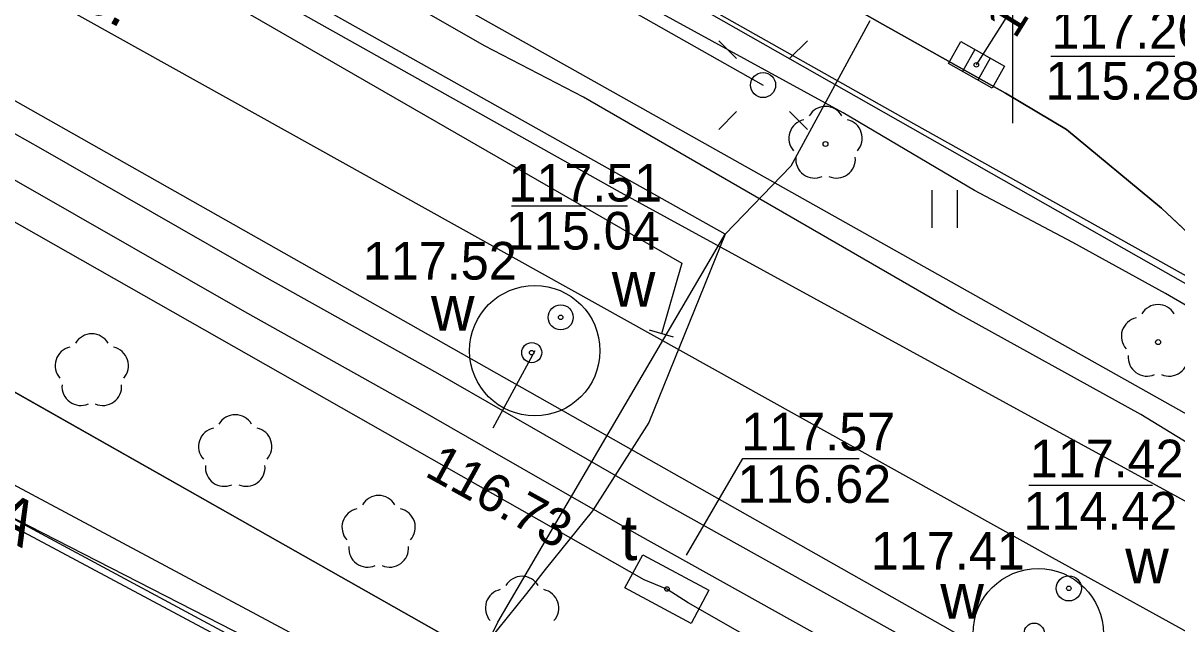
# Model space of a CAD drawing. Extents: x 6434771 to 6436222, y 5663454 to 5664782.
# Drawn here: x 6435180.26 to 6435203.28, y 5663885.02 to 5663897 of the extents above; entities that cross this region are included whole.
import ezdxf

# ---------------------------------------------------------------- set-up
doc = ezdxf.new("R2010")
doc.units = 0
for name, color, linetype in [('Warstwa 1', 7, 'Continuous'), ('Warstwa 10', 7, 'Continuous'), ('Warstwa 11', 7, 'Continuous'), ('Warstwa 12', 7, 'Continuous'), ('Warstwa 13', 7, 'Continuous'), ('Warstwa 14', 7, 'Continuous'), ('Warstwa 15', 7, 'Continuous'), ('Warstwa 2', 7, 'Continuous'), ('Warstwa 20', 7, 'Continuous'), ('Warstwa 4', 7, 'Continuous'), ('Warstwa 5', 7, 'Continuous'), ('Warstwa 6', 7, 'Continuous'), ('Warstwa 63', 7, 'Continuous'), ('Warstwa 7', 7, 'Continuous'), ('Warstwa 8', 7, 'Continuous'), ('Warstwa 9', 7, 'Continuous')]:
    doc.layers.add(name, color=color, linetype=linetype)

msp = doc.modelspace()

# ---------------------------------------------------------------- linework, layer by layer
at = {"layer": 'Warstwa 1'}
msp.add_line((6435069.683, 5663952.11), (6435199.169, 5663878.85), dxfattribs=at)
msp.add_line((6435069.683, 5663952.11), (6435199.169, 5663878.85), dxfattribs=at)
at = {"layer": 'Warstwa 10'}
for points in [[(6435097.639, 5663946.244), (6435110.23, 5663939.33), (6435134.8, 5663925.67), (6435154.54, 5663914.28), (6435171.5, 5663904.82), (6435193.4, 5663892.21), (6435192.998, 5663890.805)], [(6435182.257, 5663838.676), (6435188.304, 5663849.448), (6435193.351, 5663858.439), (6435194.278, 5663859.798), (6435191.577, 5663860.571), (6435190.64, 5663861.662), (6435194.242, 5663871.739), (6435194.776, 5663876.163), (6435192.223, 5663879.254), (6435189.657, 5663881.265), (6435188.718, 5663882.987), (6435189.733, 5663885.054), (6435194.267, 5663892.79), (6435145.165, 5663920.315), (6435099.449, 5663946.22)], [(6435276.336, 5663842.501), (6435260.05, 5663851.86), (6435249.96, 5663857.64), (6435238.71, 5663863.53), (6435238.1, 5663863.95), (6435237.79, 5663864.33), (6435236.77, 5663866.27), (6435229, 5663870.99), (6435224.85, 5663875.36), (6435224.07, 5663876.18), (6435215.14, 5663881.13), (6435208.14, 5663884.9), (6435192.12, 5663893.65), (6435170.67, 5663905.68), (6435152.15, 5663915.89), (6435146.79, 5663915.59), (6435128.02, 5663926.23), (6435125.23, 5663931.72), (6435111.04, 5663939.84), (6435099.552, 5663946.221)], [(6435276.398, 5663847.572), (6435270.914, 5663850.621), (6435269.128, 5663851.761), (6435267.523, 5663852.588), (6435261.727, 5663855.858), (6435256.855, 5663858.651), (6435248.36, 5663863.366), (6435242.1, 5663866.891), (6435238.077, 5663869.191), (6435236.318, 5663870.082), (6435231.153, 5663872.984), (6435227.254, 5663875.255), (6435219.004, 5663879.813), (6435214.473, 5663882.474), (6435208.6, 5663885.825), (6435204.743, 5663887.86), (6435202.556, 5663889.192), (6435198.825, 5663891.256), (6435191.441, 5663895.523), (6435189.466, 5663896.541), (6435185.427, 5663898.858)]]:
    msp.add_lwpolyline(points, dxfattribs=at)
at = {"layer": 'Warstwa 11'}
for centre in [(6435196.269, 5663894.586), (6435202.902, 5663890.636)]:
    msp.add_circle(centre, 0.05, dxfattribs=at)
for centre, start, end in [((6435196.269, 5663894.961), 30.1471, 149.8529), ((6435195.912, 5663894.702), 102.1471, 221.8529), ((6435196.626, 5663894.702), 318.1471, 77.8529), ((6435196.049, 5663894.283), 174.1471, 293.8529), ((6435196.489, 5663894.283), 246.1471, 5.8529), ((6435202.902, 5663891.011), 30.1471, 149.8529), ((6435202.545, 5663890.752), 102.1471, 221.8529), ((6435202.682, 5663890.333), 174.1471, 293.8529), ((6435203.122, 5663890.333), 246.1471, 5.8529)]:
    msp.add_arc(centre, 0.375, start, end, dxfattribs=at)
at = {"layer": 'Warstwa 12'}
for points in [[(6435276.296, 5663839.122), (6435202.248, 5663880.463), (6435193.528, 5663885.439), (6435193.106, 5663885.714), (6435192.653, 5663885.899), (6435159.975, 5663904.455), (6435111.809, 5663931.659), (6435087.394, 5663945.495), (6435086.953, 5663945.766), (6435086.601, 5663946.025), (6435086.024, 5663946.382)], [(6435105.187, 5663946.15), (6435115.17, 5663940.769), (6435143.559, 5663924.775), (6435168.541, 5663910.722), (6435195.023, 5663895.761)], [(6435221.655, 5663880.269), (6435221.936, 5663880.862), (6435218.575, 5663882.674), (6435218.173, 5663882.896), (6435217.302, 5663882.72), (6435214.097, 5663884.591), (6435205.693, 5663889.213), (6435205.45, 5663889.713), (6435204.961, 5663890.309), (6435204.469, 5663890.781), (6435203.051, 5663891.606), (6435201.201, 5663892.622), (6435199.242, 5663893.656), (6435196.622, 5663895.21), (6435191.749, 5663897.878), (6435189.16, 5663899.338), (6435182.205, 5663903.135), (6435181.651, 5663903.483), (6435176.748, 5663906.246), (6435171.243, 5663909.279), (6435113.962, 5663942.157), (6435109.55, 5663944.447), (6435106.279, 5663946.137)], [(6435107.26, 5663946.125), (6435127.986, 5663934.544), (6435149.124, 5663922.599), (6435165.622, 5663913.277), (6435237.784, 5663872.323), (6435252.455, 5663863.225), (6435276.408, 5663848.377)], [(6435063.696, 5663930.091), (6435072.471, 5663935.396), (6435084.159, 5663937.604), (6435099.338, 5663932.48), (6435124.367, 5663918.137), (6435165.517, 5663894.728), (6435170.23, 5663892.401), (6435196.432, 5663878.313), (6435197.764, 5663876.037), (6435200.507, 5663874.574)], [(6435243.45, 5663833.342), (6435243.347, 5663833.392), (6435243.041, 5663835.668), (6435233.883, 5663842.599), (6435229.544, 5663847.621), (6435230.488, 5663855.43), (6435227.071, 5663861.482), (6435200.606, 5663877.013), (6435196.659, 5663878.93), (6435171.937, 5663892.14), (6435164.739, 5663895.707), (6435120.054, 5663921.259), (6435106.974, 5663928.778), (6435090.917, 5663933.312), (6435076.731, 5663934.584), (6435064.319, 5663933.634), (6435061.286, 5663934.067)], [(6435184.91, 5663855.561), (6435186.088, 5663855.747), (6435193.004, 5663868.644), (6435194.726, 5663873.753), (6435194.748, 5663876.343), (6435193.834, 5663878.494), (6435189.316, 5663882.019), (6435172.175, 5663891.167), (6435167.238, 5663893.957), (6435152.766, 5663902.142), (6435132.535, 5663913.808), (6435121.373, 5663919.463), (6435119.301, 5663920.188), (6435117.575, 5663919.659), (6435117.521, 5663919.329)], [(6435154.196, 5663912.856), (6435172.328, 5663902.186), (6435172.425, 5663902.132), (6435200.789, 5663886.341), (6435214.221, 5663878.938), (6435221.693, 5663874.808)], [(6435217.331, 5663873.969), (6435211.97, 5663876.909), (6435205.465, 5663880.545), (6435200.052, 5663883.518), (6435199.858, 5663883.626), (6435192.894, 5663887.509), (6435189.829, 5663889.265), (6435188.532, 5663890.009), (6435185.07, 5663891.943), (6435180.612, 5663894.494), (6435177.758, 5663896.103), (6435171.635, 5663899.553)], [(6435171.241, 5663898.857), (6435177.366, 5663895.407), (6435180.216, 5663893.798), (6435184.676, 5663891.247), (6435188.138, 5663889.313), (6435189.431, 5663888.571), (6435192.5, 5663886.813), (6435199.47, 5663882.926), (6435199.666, 5663882.818), (6435205.077, 5663879.845), (6435211.582, 5663876.209), (6435216.939, 5663873.271)], [(6435197.155, 5663897.039), (6435195.575, 5663894.146), (6435194.267, 5663892.79), (6435192.743, 5663889.032), (6435191.62, 5663887.275), (6435190.675, 5663886.105), (6435190.304, 5663885.622), (6435189.532, 5663884.668), (6435192.509, 5663883.156), (6435194.776, 5663881.916), (6435196.042, 5663881.296), (6435200.013, 5663879.112), (6435203.507, 5663877.322), (6435206.668, 5663875.559), (6435207.316, 5663875.256), (6435208.872, 5663874.337), (6435211.964, 5663872.645), (6435216.158, 5663870.28)], [(6435167.474, 5663893.574), (6435167.841, 5663893.39), (6435189.629, 5663882.236), (6435195.77, 5663877.321), (6435196.196, 5663874.496), (6435195.406, 5663872.865), (6435192.688, 5663867.268), (6435186.52, 5663855.912), (6435184.483, 5663853.696)], [(6435190.468, 5663890.466), (6435189.63, 5663888.918)]]:
    msp.add_lwpolyline(points, dxfattribs=at)
at = {"layer": 'Warstwa 13'}
for centre, start, end in [((6435181.632, 5663890.427), 30.1471, 149.8529), ((6435181.275, 5663890.168), 102.0477, 221.9513), ((6435181.989, 5663890.168), 318.0487, 77.9523), ((6435181.412, 5663889.749), 174.1984, 293.7229), ((6435181.852, 5663889.749), 246.2771, 5.6877), ((6435184.493, 5663888.815), 30.1471, 149.8529), ((6435184.136, 5663888.556), 102.0477, 221.9513), ((6435184.85, 5663888.556), 318.0487, 77.9523), ((6435184.273, 5663888.137), 174.1984, 293.7229), ((6435184.713, 5663888.137), 246.2771, 5.6877), ((6435187.354, 5663887.204), 30.1471, 149.8529), ((6435186.997, 5663886.945), 102.0477, 221.9513), ((6435187.711, 5663886.945), 318.0487, 77.9523), ((6435187.134, 5663886.526), 174.1984, 293.7229), ((6435187.574, 5663886.526), 246.2771, 5.6877), ((6435190.215, 5663885.594), 30.1471, 149.8529), ((6435189.858, 5663885.335), 102.0477, 221.9513), ((6435190.572, 5663885.335), 318.0487, 77.9523)]:
    msp.add_arc(centre, 0.375, start, end, dxfattribs=at)
at = {"layer": 'Warstwa 14'}
for p, q in [((6435200.766, 5663896.339), (6435203.24, 5663896.339)), ((6435192.316, 5663893.348), (6435190.007, 5663893.348)), ((6435202.793, 5663887.78), (6435200.325, 5663887.78))]:
    msp.add_line(p, q, dxfattribs=at)
msp.add_lwpolyline([(6435193.494, 5663886.39), (6435194.617, 5663888.316), (6435196.943, 5663888.316)], dxfattribs=at)
for centre in [(6435199.278, 5663896.165), (6435199.278, 5663896.165), (6435190.986, 5663891.13), (6435193.106, 5663885.714), (6435193.106, 5663885.714), (6435201.122, 5663885.727)]:
    msp.add_circle(centre, 0.045, dxfattribs=at)
at = {"layer": 'Warstwa 15'}
for centre in [(6435190.468, 5663890.466), (6435200.511, 5663884.824)]:
    msp.add_circle(centre, 1.3, dxfattribs=at)
at = {"layer": 'Warstwa 2'}
msp.add_lwpolyline([(6435200.658, 5663880.452), (6435199.759, 5663878.873), (6435199.169, 5663878.85), (6435121.486, 5663922.801), (6435118.054, 5663924.603)], dxfattribs=at)
msp.add_circle((6435195.023, 5663895.761), 0.25, dxfattribs=at)
at = {"layer": 'Warstwa 20'}
msp.add_line((6435193.238, 5663890.736), (6435192.758, 5663890.874), dxfattribs=at)
at = {"layer": 'Warstwa 4'}
for p, q in [((6435199.248, 5663896.469), (6435199.003, 5663896.033)), ((6435199.553, 5663896.297), (6435199.308, 5663895.861))]:
    msp.add_line(p, q, dxfattribs=at)
for points in [[(6435194.493, 5663896.291), (6435194.139, 5663896.645)], [(6435195.553, 5663896.291), (6435195.907, 5663896.645)], [(6435194.493, 5663895.231), (6435194.139, 5663894.877)], [(6435195.553, 5663895.231), (6435195.907, 5663894.877)]]:
    msp.add_lwpolyline(points, dxfattribs=at)
for points in [[(6435198.965, 5663896.628), (6435199.836, 5663896.137), (6435199.591, 5663895.702), (6435198.72, 5663896.193)], [(6435192.268, 5663885.738), (6435192.622, 5663886.399), (6435193.944, 5663885.69), (6435193.59, 5663885.029)]]:
    msp.add_lwpolyline(points, close=True, dxfattribs=at)
for centre, radius in [((6435190.986, 5663891.13), 0.25), ((6435190.408, 5663890.427), 0.2), ((6435201.122, 5663885.727), 0.25), ((6435200.431, 5663884.835), 0.2)]:
    msp.add_circle(centre, radius, dxfattribs=at)
at = {"layer": 'Warstwa 5'}
for p, q in [((6435138.996, 5663925.41), (6435208.52, 5663886.367)), ((6435190.115, 5663899.453), (6435198.021, 5663894.995)), ((6435198.021, 5663894.995), (6435205.614, 5663890.756)), ((6435198.399, 5663892.915), (6435198.399, 5663893.665)), ((6435198.899, 5663892.915), (6435198.899, 5663893.665))]:
    msp.add_line(p, q, dxfattribs=at)
at = {"layer": 'Warstwa 6'}
for points in [[(6435069.683, 5663952.11), (6435199.169, 5663878.85), (6435199.759, 5663878.873), (6435200.658, 5663880.452), (6435202.784, 5663879.266), (6435210.691, 5663874.851), (6435241.929, 5663857.022), (6435237.4, 5663848.916), (6435242.169, 5663846.309), (6435246.778, 5663854.403), (6435284.269, 5663833.48)], [(6435180.355, 5663839.798), (6435199.977, 5663874.56), (6435202.784, 5663879.266), (6435200.658, 5663880.452), (6435199.759, 5663878.873), (6435199.169, 5663878.85), (6435069.683, 5663952.11)], [(6435205.022, 5663891.385), (6435202.968, 5663893.304), (6435201.077, 5663894.877), (6435199.856, 5663895.599), (6435197.402, 5663896.978), (6435191.147, 5663900.524)]]:
    msp.add_lwpolyline(points, dxfattribs=at)
for centre in [(6435199.278, 5663896.165), (6435190.986, 5663891.13), (6435190.408, 5663890.427), (6435193.106, 5663885.714), (6435201.122, 5663885.727)]:
    msp.add_circle(centre, 0.045, dxfattribs=at)
at = {"layer": 'Warstwa 63'}
msp.add_line((6435200, 5663905), (6435200, 5663895), dxfattribs=at)
at = {"layer": 'Warstwa 7'}
msp.add_lwpolyline([(6435199.278, 5663896.165), (6435205.379, 5663905.778)], dxfattribs=at)
at = {"layer": 'Warstwa 8'}
for p, q in [((6435191.147, 5663900.524), (6435197.402, 5663896.978)), ((6435197.402, 5663896.978), (6435199.856, 5663895.599)), ((6435199.856, 5663895.599), (6435201.077, 5663894.877)), ((6435201.077, 5663894.877), (6435202.968, 5663893.304)), ((6435202.968, 5663893.304), (6435205.022, 5663891.385))]:
    msp.add_line(p, q, dxfattribs=at)
at = {"layer": 'Warstwa 9'}
for p, q in [((6435138.996, 5663925.41), (6435208.52, 5663886.367)), ((6435135.707, 5663920.53), (6435203.182, 5663882.402)), ((6435191.147, 5663900.524), (6435197.402, 5663896.978)), ((6435190.115, 5663899.453), (6435198.021, 5663894.995)), ((6435197.402, 5663896.978), (6435199.856, 5663895.599)), ((6435199.856, 5663895.599), (6435201.077, 5663894.877)), ((6435198.021, 5663894.995), (6435205.614, 5663890.756)), ((6435201.077, 5663894.877), (6435202.968, 5663893.304)), ((6435202.968, 5663893.304), (6435205.022, 5663891.385))]:
    msp.add_line(p, q, dxfattribs=at)

# ---------------------------------------------------------------- texts
at = {"layer": 'Warstwa 13'}
msp.add_text('eNA', height=0.9, rotation=332.4244, dxfattribs=at).set_placement((6435178.173, 5663887.608))
at = {"layer": 'Warstwa 14'}
for s, rotation, p in [('116.13', 58.2927, (6435200.052, 5663896.661)), ('116.73', 331.1009, (6435188.248, 5663887.981))]:
    msp.add_text(s, height=0.75, rotation=rotation, dxfattribs=at).set_placement(p)
for s, p in [('115.28', (6435200.659, 5663895.473)), ('115.04', (6435189.893, 5663892.483)), ('116.62', (6435194.511, 5663887.433)), ('114.42', (6435200.219, 5663886.899))]:
    msp.add_text(s, height=0.75, dxfattribs=at).set_placement(p)
at = {"layer": 'Warstwa 5'}
for s, p in [('w', (6435192.005, 5663891.343)), ('w', (6435188.398, 5663890.868)), ('t', (6435192.181, 5663886.29)), ('w', (6435202.247, 5663885.829)), ('w', (6435198.559, 5663885.124))]:
    msp.add_text(s, height=0.9, dxfattribs=at).set_placement(p)
at = {"layer": 'Warstwa 6'}
for s, p in [('117.26', (6435200.774, 5663896.487)), ('117.51', (6435189.943, 5663893.44)), ('117.52', (6435187.041, 5663891.884)), ('117.57', (6435194.589, 5663888.477)), ('117.42', (6435200.344, 5663887.942)), ('117.41', (6435197.175, 5663886.102))]:
    msp.add_text(s, height=0.75, dxfattribs=at).set_placement(p)
at = {"layer": 'Warstwa 9'}
msp.add_text('ch.mb.', height=0.9, rotation=331.2212, dxfattribs=at).set_placement((6435179.052, 5663898.622))

doc.saveas('drawing.dxf')
